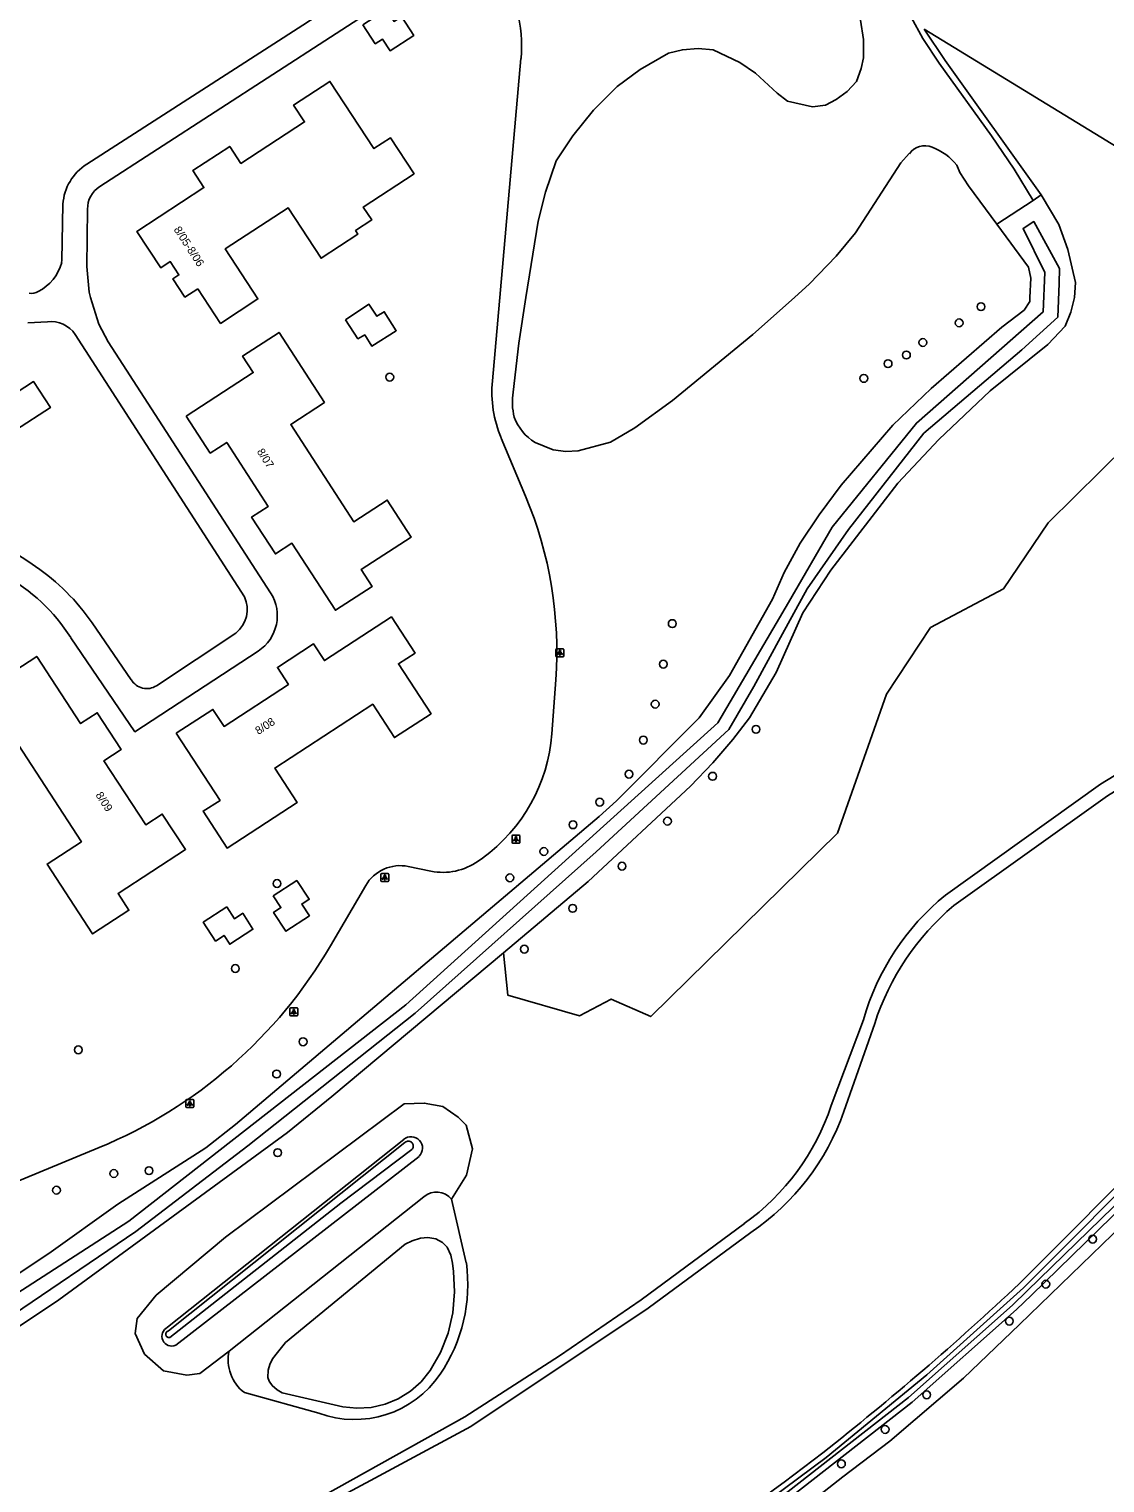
# Model space of a CAD drawing. Extents: x 159451 to 160663, y 388402 to 389723.
# Drawn here: x 160094.7 to 160229.1, y 389101.8 to 389283.5 of the extents above; entities that cross this region are included whole.
import ezdxf

# ---------------------------------------------------------------- set-up
doc = ezdxf.new("R2010")
doc.units = 0
for name, color, linetype in [('IMGEO_Boom', 7, 'Continuous'), ('IMGEO_Grasland_overig', 7, 'Continuous'), ('IMGEO_Groenvoorziening', 7, 'Continuous'), ('IMGEO_Lichtpunt', 7, 'Continuous'), ('IMGEO_Loofbos', 7, 'Continuous'), ('IMGEO_Meer_plas_ven_vijver', 7, 'Continuous'), ('IMGEO_Oever', 7, 'Continuous'), ('IMGEO_Pand', 7, 'Continuous'), ('IMGEO_Pand_nummerreeks', 7, 'Continuous'), ('IMGEO_Rijbaan_lokaal_halfverhard', 7, 'Continuous'), ('IMGEO_Stuw', 7, 'Continuous'), ('IMGEO_Voetpad_gesloten', 7, 'Continuous'), ('IMGEO_Voetpad_halfverhard', 7, 'Continuous'), ('IMGEO_Waterloop', 7, 'Continuous')]:
    doc.layers.add(name, color=color, linetype=linetype)

msp = doc.modelspace()

# ---------------------------------------------------------------- linework, layer by layer
at = {"layer": 'IMGEO_Boom'}
for centre in [(160213.65, 389248.84), (160210.92, 389246.82), (160206.39, 389244.37), (160204.33, 389242.81), (160202.04, 389241.72), (160139.77, 389240.04), (160199.01, 389239.88), (160175.07, 389209.24), (160173.96, 389204.17), (160172.94, 389199.17), (160185.54, 389196.03), (160171.45, 389194.68), (160169.66, 389190.42), (160180.11, 389190.16), (160166.01, 389186.93), (160174.47, 389184.54), (160162.67, 389184.1), (160159.03, 389180.76), (160168.79, 389178.92), (160154.78, 389177.47), (160125.68, 389176.75), (160162.62, 389173.65), (160156.58, 389168.55), (160120.48, 389166.13), (160128.94, 389156.98), (160100.86, 389155.97), (160125.63, 389152.95), (160125.77, 389143.12), (160109.68, 389140.87), (160105.29, 389140.51), (160098.12, 389138.43), (160227.6, 389132.31), (160221.75, 389126.69), (160217.19, 389122.07), (160206.86, 389112.86), (160201.67, 389108.53), (160196.21, 389104.23)]:
    msp.add_circle(centre, 0.489, dxfattribs=at)
at = {"layer": 'IMGEO_Grasland_overig'}
for points in [[(160303.21, 389231.29), (160307.12, 389228.25), (160314.14, 389218.62), (160309.81, 389214.07), (160301.6, 389205.46), (160273.12, 389177.69), (160256.82, 389161.25), (160219.95, 389125.33), (160218.1, 389123.51), (160205.06, 389111.96), (160182.96, 389094.71), (160158.93, 389077.52), (160133.47, 389059.66), (160123.11, 389052.98), (160107.1, 389044.45), (160100.34, 389041.48)], [(160297.29, 389224.18), (160308.31, 389215.35), (160286.76, 389193.38), (160235.96, 389144.29), (160218.46, 389126.75)], [(160153.98, 389168.11), (160132.54, 389150.12), (160127.01, 389145.62), (160098.42, 389124.73), (160085.71, 389116.26), (160061.52, 389101.37)], [(160119.69, 389118.33), (160116.03, 389115.52), (160114.43, 389115.32), (160111.48, 389115.84), (160109.11, 389117.95), (160107.95, 389120.52), (160108.21, 389122.38), (160110.58, 389125.33), (160119.24, 389132.58), (160141.56, 389149.23), (160144.09, 389149.31), (160146.4, 389148.91), (160148.31, 389147.55), (160149.31, 389146.54), (160150.11, 389143.6), (160149.34, 389140.32), (160147.5, 389137.31)], [(160141.51, 389144.78), (160112.01, 389121.3)], [(160113.03, 389119.05), (160143.43, 389142.66)], [(160144.04, 389137.61), (160119.69, 389118.33)], [(160147.5, 389137.31), (160149.33, 389129.36)], [(160130.89, 389110.56), (160121.61, 389113.13)]]:
    msp.add_lwpolyline(points, dxfattribs=at)
for centre, radius, start, end in [((160142.43, 389143.69), 1.43, 314.1679, 130.3633), ((160145.62, 389135.73), 2.46, 40.0396, 130.0067), ((160129.47, 389126.67), 20.05, 325.9078, 7.697), ((159960.35, 389401.94), 377.29, 308.2389, 313.1649), ((160112.53, 389120.18), 1.23, 115.2608, 293.8614), ((160124.73, 389117.24), 5.16, 167.7834, 232.7817), ((160135.37, 389122.7), 12.93, 249.7467, 325.841), ((159649.6, 389819.15), 897.43, 304.25394, 307.33539)]:
    msp.add_arc(centre, radius, start, end, dxfattribs=at)
at = {"layer": 'IMGEO_Groenvoorziening'}
msp.add_lwpolyline([(160090.89, 389236.66), (160093.01, 389233.4), (160097.37, 389236.23), (160095.26, 389239.49), (160090.89, 389236.66)], dxfattribs=at)
at = {"layer": 'IMGEO_Lichtpunt'}
for p, q in [((160160.53, 389205.99), (160160.53, 389205.19)), ((160160.53, 389205.99), (160160.53, 389205.19)), ((160161.43, 389206.09), (160160.62, 389206.09)), ((160161.43, 389206.09), (160160.62, 389206.09)), ((160160.62, 389205.09), (160161.43, 389205.09)), ((160160.62, 389205.09), (160161.43, 389205.09)), ((160161.52, 389205.19), (160161.52, 389205.99)), ((160161.52, 389205.19), (160161.52, 389205.99)), ((160155.95, 389182.79), (160155.14, 389182.79)), ((160155.95, 389182.79), (160155.14, 389182.79)), ((160155.05, 389182.7), (160155.05, 389181.89)), ((160155.05, 389182.7), (160155.05, 389181.89)), ((160155.14, 389181.8), (160155.95, 389181.8)), ((160155.14, 389181.8), (160155.95, 389181.8)), ((160156.04, 389181.89), (160156.04, 389182.7)), ((160156.04, 389181.89), (160156.04, 389182.7)), ((160138.65, 389177.91), (160138.65, 389177.11)), ((160138.65, 389177.91), (160138.65, 389177.11)), ((160139.55, 389178.01), (160138.75, 389178.01)), ((160139.55, 389178.01), (160138.75, 389178.01)), ((160139.65, 389177.11), (160139.65, 389177.91)), ((160139.65, 389177.11), (160139.65, 389177.91)), ((160138.75, 389177.01), (160139.55, 389177.01)), ((160138.75, 389177.01), (160139.55, 389177.01)), ((160127.28, 389161.12), (160127.28, 389160.31)), ((160127.28, 389161.12), (160127.28, 389160.31)), ((160128.18, 389161.21), (160127.38, 389161.21)), ((160128.18, 389161.21), (160127.38, 389161.21)), ((160128.28, 389160.31), (160128.28, 389161.12)), ((160128.28, 389160.31), (160128.28, 389161.12)), ((160127.38, 389160.22), (160128.18, 389160.22)), ((160127.38, 389160.22), (160128.18, 389160.22)), ((160114.28, 389149.66), (160114.28, 389148.86)), ((160114.28, 389149.66), (160114.28, 389148.86)), ((160115.19, 389149.76), (160114.38, 389149.76)), ((160115.19, 389149.76), (160114.38, 389149.76)), ((160114.38, 389148.76), (160115.19, 389148.76)), ((160114.38, 389148.76), (160115.19, 389148.76)), ((160115.28, 389148.86), (160115.28, 389149.66)), ((160115.28, 389148.86), (160115.28, 389149.66))]:
    msp.add_line(p, q, dxfattribs=at)
for points in [[(160160.9, 389205.66), (160160.94, 389205.63), (160160.75, 389205.37), (160160.71, 389205.4), (160160.9, 389205.66)], [(160161, 389205.61), (160161.05, 389205.61), (160161.05, 389205.29), (160161, 389205.29), (160161, 389205.61)], [(160161.11, 389205.63), (160161.15, 389205.66), (160161.34, 389205.39), (160161.3, 389205.37), (160161.11, 389205.63)], [(160155.42, 389182.36), (160155.46, 389182.33), (160155.27, 389182.07), (160155.23, 389182.1), (160155.42, 389182.36)], [(160155.52, 389182.31), (160155.57, 389182.31), (160155.57, 389181.99), (160155.52, 389181.99), (160155.52, 389182.31)], [(160155.63, 389182.33), (160155.67, 389182.36), (160155.86, 389182.1), (160155.82, 389182.07), (160155.63, 389182.33)], [(160139.03, 389177.58), (160139.06, 389177.55), (160138.88, 389177.29), (160138.84, 389177.31), (160139.03, 389177.58)], [(160139.13, 389177.53), (160139.17, 389177.53), (160139.17, 389177.21), (160139.13, 389177.21), (160139.13, 389177.53)], [(160139.24, 389177.55), (160139.28, 389177.58), (160139.46, 389177.31), (160139.42, 389177.29), (160139.24, 389177.55)], [(160127.66, 389160.78), (160127.69, 389160.75), (160127.51, 389160.49), (160127.47, 389160.52), (160127.66, 389160.78)], [(160127.76, 389160.73), (160127.81, 389160.73), (160127.81, 389160.41), (160127.76, 389160.41), (160127.76, 389160.73)], [(160127.87, 389160.75), (160127.91, 389160.78), (160128.09, 389160.52), (160128.05, 389160.49), (160127.87, 389160.75)], [(160114.66, 389149.33), (160114.7, 389149.3), (160114.51, 389149.04), (160114.47, 389149.07), (160114.66, 389149.33)], [(160114.76, 389149.28), (160114.81, 389149.28), (160114.81, 389148.96), (160114.76, 389148.96), (160114.76, 389149.28)], [(160114.87, 389149.3), (160114.91, 389149.33), (160115.1, 389149.06), (160115.06, 389149.04), (160114.87, 389149.3)]]:
    msp.add_lwpolyline(points, dxfattribs=at)
for centre in [(160161.03, 389205.79), (160155.55, 389182.5), (160139.15, 389177.71), (160127.78, 389160.92), (160114.78, 389149.46)]:
    msp.add_circle(centre, 0.0994, dxfattribs=at)
for centre, start, end in [((160160.62, 389205.99), 90, 180), ((160160.62, 389205.99), 90, 180), ((160160.62, 389205.19), 180, 270), ((160160.62, 389205.19), 180, 270), ((160161.43, 389205.99), 0, 90), ((160161.43, 389205.99), 0, 90), ((160161.43, 389205.19), 270, 0), ((160161.43, 389205.19), 270, 360), ((160155.14, 389182.7), 90, 180), ((160155.14, 389182.7), 90, 180), ((160155.95, 389182.7), 0, 90), ((160155.95, 389182.7), 0, 90), ((160155.14, 389181.89), 180, 270), ((160155.14, 389181.89), 180, 270), ((160155.95, 389181.89), 270, 0), ((160155.95, 389181.89), 270, 360), ((160138.75, 389177.91), 90, 180), ((160138.75, 389177.91), 90, 180), ((160139.55, 389177.91), 0, 90), ((160139.55, 389177.91), 0, 90), ((160138.75, 389177.11), 180, 270), ((160138.75, 389177.11), 180, 270), ((160139.55, 389177.11), 270, 0), ((160139.55, 389177.11), 270, 360), ((160127.38, 389161.12), 90, 180), ((160127.38, 389161.12), 90, 180), ((160128.18, 389161.12), 0, 90), ((160128.18, 389161.12), 0, 90), ((160127.38, 389160.31), 180, 270), ((160127.38, 389160.31), 180, 270), ((160128.18, 389160.31), 270, 0), ((160128.18, 389160.31), 270, 360), ((160114.38, 389149.66), 90, 180), ((160114.38, 389149.66), 90, 180), ((160114.38, 389148.86), 180, 270), ((160114.38, 389148.86), 180, 270), ((160115.19, 389149.66), 0, 90), ((160115.19, 389149.66), 0, 90), ((160115.19, 389148.86), 270, 0), ((160115.19, 389148.86), 270, 360)]:
    msp.add_arc(centre, 0.0946, start, end, dxfattribs=at)
at = {"layer": 'IMGEO_Loofbos'}
for points in [[(160206.57, 389283.54), (160209.19, 389279.61), (160221.19, 389262.82)], [(160206.57, 389283.54), (160243.22, 389261.1)], [(160156.17, 389279.87), (160152.59, 389239.57)], [(160221.19, 389262.82), (160223.37, 389259.1), (160224.52, 389255.99), (160225.46, 389251.86), (160225.35, 389250), (160224.89, 389248.16), (160224.15, 389246.43), (160222, 389244.13), (160214.8, 389238.32), (160208.39, 389232.26), (160203.24, 389226.79), (160194.88, 389215.93), (160191.39, 389210.6), (160188.07, 389203.13), (160184.71, 389197.48), (160182.66, 389194.76), (160180.13, 389191.82), (160177.34, 389188.93), (160164.55, 389176.99), (160153.98, 389168.11)], [(160243.22, 389261.1), (160235.19, 389234.83), (160222.06, 389221.82), (160216.45, 389213.58), (160207.36, 389208.75), (160201.86, 389200.44), (160195.71, 389183.04), (160172.39, 389160.12), (160167.44, 389162.32), (160163.48, 389160.23), (160154.54, 389162.79), (160153.98, 389168.11)], [(160087.85, 389124.34), (160097.16, 389130.51), (160105.79, 389136.67), (160116.79, 389143.72), (160120.48, 389146.62), (160165.95, 389185.12), (160168.11, 389187.1), (160178.43, 389197.48), (160182.22, 389202.77), (160187.6, 389212.28), (160189.05, 389215.64), (160191.05, 389219.31), (160193.43, 389222.84), (160196.19, 389226.54), (160202.65, 389234.04), (160207.42, 389238.61), (160216.26, 389246.29), (160219.05, 389248.41), (160219.75, 389249.51), (160219.77, 389250), (160219.9, 389252.39), (160219.6, 389253.79), (160215.62, 389259.16)], [(160153.7, 389232.43), (160156.75, 389225.17)], [(160160.51, 389202.2), (160160.02, 389195.47)], [(160151.35, 389179.94), (160150.81, 389179.56)], [(160144.92, 389178.3), (160142.09, 389178.89)], [(160136.77, 389176.51), (160132.36, 389168.97)], [(160103.46, 389143.76), (160091.31, 389138.74)]]:
    msp.add_lwpolyline(points, dxfattribs=at)
for centre, radius, start, end in [((160138.74, 389281.42), 17.5, 354.9256, 34.6003), ((160167.54, 389238.24), 15.01, 174.9351, 202.7576), ((160110.63, 389205.82), 50.01, 355.8467, 22.7665), ((160139.08, 389196.99), 21, 305.7403, 355.8432), ((160146.43, 389185.65), 7.5, 258.3604, 305.7362), ((160141.08, 389173.99), 5, 78.3578, 149.7367), ((160080.54, 389199.21), 60, 292.4572, 329.7288)]:
    msp.add_arc(centre, radius, start, end, dxfattribs=at)
at = {"layer": 'IMGEO_Meer_plas_ven_vijver'}
for points in [[(160092.92, 389353.53), (160100.93, 389352.39), (160107.65, 389351.18), (160112.58, 389350.05), (160122.77, 389347.24), (160127.96, 389345.31), (160132.96, 389343.2), (160138.64, 389340.56), (160149.72, 389334.34), (160156.42, 389329.87), (160162.3, 389325.29), (160173.91, 389315.69), (160190.85, 389302.63), (160195.99, 389298.18), (160201.06, 389292.96), (160203.4, 389289.02), (160204.94, 389285.02), (160206.39, 389282.38), (160208.43, 389279.28), (160214.98, 389270.21), (160217.78, 389266.04), (160220.17, 389262.1)], [(160155.18, 389238.18), (160155.88, 389244.29), (160156.79, 389250), (160158.3, 389259.54), (160159.23, 389263.15), (160160.57, 389267.08), (160162.65, 389270.2), (160165.24, 389273.42), (160168.17, 389276.37), (160171.05, 389278.5), (160174.62, 389280.54), (160176.34, 389280.95), (160178.3, 389281.09), (160180.2, 389280.93), (160183.53, 389279.37), (160185.46, 389278.03), (160188.19, 389275.52), (160189.46, 389274.53), (160192.6, 389273.82), (160194.24, 389274.04), (160195.57, 389274.75), (160196.94, 389275.72), (160198.11, 389276.99), (160198.69, 389278.62), (160198.96, 389279.96), (160198.97, 389282.24), (160198.59, 389284.66)], [(160204.69, 389267.97), (160203.64, 389266.82), (160197.96, 389258.06), (160195.55, 389255.14), (160192.22, 389251.69), (160190.33, 389250), (160185.15, 389245.38), (160175.12, 389237.12), (160170.38, 389233.72), (160167.34, 389231.91), (160163.33, 389230.85), (160161.77, 389230.75), (160160.19, 389230.96), (160157.94, 389231.85)], [(160215.62, 389259.16), (160212.09, 389263.94), (160210.99, 389265.61), (160210.62, 389266.53)], [(160220.17, 389262.1), (160215.62, 389259.16)], [(160112.3, 389120.04), (160133.65, 389136.79), (160142.54, 389143.51), (160142.6, 389143.58), (160142.65, 389143.67), (160142.69, 389143.77), (160142.71, 389143.87), (160142.71, 389143.98), (160142.7, 389144.08), (160142.67, 389144.18), (160142.62, 389144.27), (160142.56, 389144.35), (160142.48, 389144.42), (160142.39, 389144.48), (160142.3, 389144.52), (160142.2, 389144.55), (160142.09, 389144.55), (160141.99, 389144.54), (160141.89, 389144.51), (160141.79, 389144.47), (160141.67, 389144.38), (160112.14, 389120.87), (160111.95, 389120.77), (160111.9, 389120.73), (160111.85, 389120.67), (160111.82, 389120.61), (160111.79, 389120.54), (160111.78, 389120.47), (160111.78, 389120.4), (160111.79, 389120.33), (160111.81, 389120.26), (160111.85, 389120.2), (160111.89, 389120.14), (160111.95, 389120.09), (160112.01, 389120.06), (160112.08, 389120.03), (160112.15, 389120.02), (160112.22, 389120.02), (160112.29, 389120.03), (160112.3, 389120.04)], [(160141.68, 389131.69), (160142.58, 389132.09), (160143.62, 389132.42), (160144.51, 389132.52), (160145.54, 389132.36), (160146.36, 389131.9), (160146.95, 389131.29), (160147.42, 389130.29), (160147.62, 389129.31), (160147.72, 389128.29), (160147.88, 389125.71), (160147.66, 389123.11), (160147.07, 389120.58), (160146.11, 389118.15), (160144.82, 389115.9), (160143.69, 389114.5), (160142.35, 389113.32), (160140.84, 389112.37), (160139.19, 389111.69), (160137.45, 389111.28), (160135.67, 389111.17), (160133.89, 389111.36), (160126.34, 389113.12), (160125.71, 389113.5), (160125.09, 389114.01), (160124.71, 389114.56), (160124.54, 389115.04), (160124.57, 389115.94), (160124.8, 389116.65), (160125.13, 389117.36), (160125.75, 389118.15), (160126.25, 389118.77), (160126.75, 389119.39), (160141.68, 389131.69)]]:
    msp.add_lwpolyline(points, dxfattribs=at)
for centre, radius, start, end in [((160206.62, 389266.63), 2.34, 66.2389, 145.2085), ((160205.08, 389262.18), 7.05, 38.0712, 69.3416), ((160162.87, 389236.98), 7.78, 171.1259, 194.4221), ((160161.14, 389237.13), 6.17, 199.7556, 238.7665)]:
    msp.add_arc(centre, radius, start, end, dxfattribs=at)
at = {"layer": 'IMGEO_Oever'}
msp.add_lwpolyline([(160221.19, 389262.82), (160220.17, 389262.1)], dxfattribs=at)
at = {"layer": 'IMGEO_Pand'}
for points in [[(160136.41, 389284.05), (160139.35, 389285.97), (160140.31, 389284.5), (160141.22, 389285.1), (160142.76, 389282.74), (160139.82, 389280.82), (160138.86, 389282.29), (160137.95, 389281.7), (160136.41, 389284.05)], [(160115.79, 389251.09), (160114.18, 389250.04), (160112.68, 389252.33), (160113.43, 389252.82), (160112.33, 389254.49), (160111.15, 389253.71), (160108.18, 389258.25), (160116.55, 389263.72), (160115.16, 389265.85), (160119.78, 389268.87), (160121.18, 389266.74), (160129.13, 389271.94), (160127.76, 389274.04), (160132.3, 389277), (160137.8, 389268.6), (160139.86, 389269.95), (160142.81, 389265.45), (160136.46, 389261.3), (160137.52, 389259.69), (160135.49, 389258.36), (160135.79, 389257.91), (160131.18, 389254.89), (160127.06, 389261.2), (160119.21, 389256.07), (160123.3, 389249.81), (160118.62, 389246.75), (160115.79, 389251.09)], [(160134.23, 389247.21), (160137.16, 389249.15), (160138.16, 389247.64), (160139.09, 389248.22), (160140.58, 389245.83), (160137.52, 389243.91), (160136.64, 389245.31), (160135.8, 389244.84), (160134.23, 389247.21)], [(160114.34, 389235.18), (160122.72, 389240.6), (160121.38, 389242.68), (160125.94, 389245.63), (160131.61, 389236.87), (160127.39, 389234.14), (160135.27, 389221.97), (160139.46, 389224.68), (160142.45, 389220.05), (160136.21, 389216.01), (160137.59, 389213.88), (160132.98, 389210.9), (160127.55, 389219.29), (160125.48, 389217.95), (160122.5, 389222.55), (160124.58, 389223.89), (160119.41, 389231.88), (160117.34, 389230.54), (160114.34, 389235.18)], [(160113.1, 389195.53), (160117.68, 389198.51), (160119.06, 389196.39), (160127.11, 389201.64), (160125.73, 389203.76), (160130.25, 389206.7), (160131.61, 389204.62), (160139.98, 389210.08), (160142.93, 389205.56), (160140.86, 389204.22), (160144.93, 389197.97), (160140.36, 389194.99), (160137.64, 389199.16), (160125.4, 389191.18), (160128.19, 389186.88), (160119.44, 389181.19), (160116.45, 389185.8), (160118.56, 389187.15), (160113.1, 389195.53)], [(160093.32, 389194.12), (160089.09, 389191.36), (160086.16, 389195.94), (160092.5, 389200.07), (160091.12, 389202.18), (160095.66, 389205.14), (160101.13, 389196.74), (160103.22, 389198.1), (160106.21, 389193.51), (160104.05, 389192.1), (160109.28, 389184.09), (160111.35, 389185.44), (160114.25, 389181.01), (160105.82, 389175.51), (160107.18, 389173.42), (160102.63, 389170.46), (160096.94, 389179.18), (160101.23, 389181.98), (160093.32, 389194.12)], [(160125.21, 389175.22), (160128.15, 389177.13), (160129.7, 389174.78), (160128.78, 389174.19), (160129.74, 389172.72), (160126.8, 389170.8), (160125.25, 389173.15), (160126.17, 389173.74), (160125.21, 389175.22)], [(160119.4, 389173.83), (160120.36, 389172.36), (160121.4, 389173.03), (160122.68, 389171.05), (160119.78, 389169.17), (160119.07, 389170.26), (160118.01, 389169.57), (160116.46, 389171.92), (160119.4, 389173.83)]]:
    msp.add_lwpolyline(points, dxfattribs=at)
at = {"layer": 'IMGEO_Rijbaan_lokaal_halfverhard'}
msp.add_lwpolyline([(160314.71, 389216.45), (160308.72, 389209.64), (160300.69, 389201.73), (160292.65, 389193.99), (160281.89, 389183.59), (160243, 389145.38), (160218.48, 389121.66), (160211.46, 389114.94), (160202.25, 389107.08), (160196.4, 389102.59), (160186.88, 389095.16), (160147.13, 389067.13), (160123.31, 389050.09), (160103.16, 389039.83), (160084.65, 389032.14), (160073.3, 389027.55), (160055.89, 389021.51), (160032.17, 389013.82), (160013.02, 389007.59), (159988.06, 388998.33), (159980.69, 388995.27), (159968.64, 388989.86), (159964.17, 388987.82)], dxfattribs=at)
at = {"layer": 'IMGEO_Stuw'}
msp.add_lwpolyline([(160215.62, 389259.16), (160220.17, 389262.1), (160221.19, 389262.82)], dxfattribs=at)
at = {"layer": 'IMGEO_Voetpad_gesloten'}
for points in [[(160143.21, 389293.69), (160143.07, 389293.23), (160142.74, 389292.86), (160141.55, 389292.33), (160128.9, 389284.01), (160101.9, 389266.65)], [(160103.54, 389263.85), (160146.77, 389291.91)], [(160098.92, 389261.66), (160098.81, 389254.61), (160098.77, 389254.36)], [(160124.88, 389213.09), (160104.59, 389244.47), (160103.43, 389246.67), (160102.39, 389250), (160102.19, 389250.64), (160101.9, 389253.88), (160102, 389261.03)], [(160094.53, 389246.84), (160096.99, 389246.95)], [(160100.46, 389245.36), (160121.6, 389212.58)], [(160107.47, 389202.22), (160102.58, 389209.35)], [(160099.9, 389207.48), (160107.92, 389195.73), (160123.31, 389205.79)], [(160120.55, 389208.05), (160110.62, 389201.47)]]:
    msp.add_lwpolyline(points, dxfattribs=at)
for centre, radius, start, end in [((160105.32, 389261.22), 6.41, 122.2326, 176.0667), ((160105.31, 389261.06), 3.31, 122.4721, 180.4297), ((160093.21, 389255.85), 5.76, 297.188, 345.0559), ((160095.06, 389252.03), 1.52, 256.3148, 300.8302), ((160097.49, 389243.45), 3.53, 32.7801, 98.2227), ((160059.62, 389163.99), 63.5, 55.5826, 70.1199), ((160079.89, 389193.56), 27.64, 34.8129, 55.5935), ((160081.39, 389195.93), 21.82, 31.964, 62.3071), ((160118.17, 389210.99), 3.79, 308.901, 24.8278), ((160120.43, 389210.23), 5.29, 302.9705, 32.6845), ((160109.4, 389203.33), 2.22, 209.994, 303.2571)]:
    msp.add_arc(centre, radius, start, end, dxfattribs=at)
at = {"layer": 'IMGEO_Voetpad_halfverhard'}
for points in [[(160209.22, 389175.31), (160228.58, 389189.18), (160253.29, 389204.19)], [(160254.21, 389202.95), (160229.46, 389187.72), (160210.25, 389173.99)], [(160194.94, 389149.01), (160198.96, 389159.71)], [(160200.38, 389159.26), (160196.51, 389148.27)], [(160131.62, 389100.32), (160149.17, 389110.1), (160160.99, 389117.75), (160171.18, 389124.72), (160184.08, 389134.26)], [(160184.89, 389133.16), (160172.05, 389123.69), (160149.9, 389108.91), (160132.42, 389099.48)]]:
    msp.add_lwpolyline(points, dxfattribs=at)
for centre, radius, start, end in [((160228.68, 389151.33), 30.88, 129.0758, 164.2559), ((160230.75, 389149.57), 31.88, 130.0092, 162.3132), ((160166.75, 389158.4), 29.71, 305.6677, 341.571), ((160167.92, 389158.23), 30.28, 304.1012, 340.7792)]:
    msp.add_arc(centre, radius, start, end, dxfattribs=at)
at = {"layer": 'IMGEO_Waterloop'}
for points in [[(160091.59, 389122.12), (160108.05, 389133.27), (160122.02, 389143.99), (160142.96, 389160.56), (160165.55, 389180.72), (160182.15, 389196.01), (160185.28, 389201.38), (160188.84, 389207.95), (160191.93, 389213.59), (160197.1, 389221), (160206.52, 389233.05), (160218.77, 389243.44), (160223.25, 389247.53), (160223.4, 389251.74), (160223.48, 389253.63), (160220.25, 389259.47), (160218.92, 389258.62), (160221.64, 389253.13), (160221.41, 389248.19), (160205.58, 389234.29), (160195.07, 389221.31), (160189.59, 389211.89), (160180.78, 389196.82), (160141.78, 389161.6), (160107.18, 389134.57), (160077.82, 389115.65)], [(160256.31, 389161.77), (160219.44, 389125.85), (160217.6, 389124.05), (160204.59, 389112.52), (160182.52, 389095.29), (160158.51, 389078.11), (160133.06, 389060.26), (160122.74, 389053.61), (160106.78, 389045.11), (160101.24, 389042.68)], [(160174.92, 389090.63), (160194.32, 389105.02), (160206.87, 389115.35), (160218.96, 389126.22), (160236.47, 389143.77)]]:
    msp.add_lwpolyline(points, dxfattribs=at)

# ---------------------------------------------------------------- texts
at = {"layer": 'IMGEO_Pand_nummerreeks'}
for s, rotation, p in [('8/05-8/06', 303.0668, (160112.73, 389258.48)), ('8/07', 302.8437, (160123.12, 389230.73)), ('8/08', 33.0674, (160123.36, 389195.31)), ('8/09', 303.0763, (160102.96, 389187.81))]:
    msp.add_text(s, height=1, rotation=rotation, dxfattribs=at).set_placement(p)

doc.saveas('drawing.dxf')
